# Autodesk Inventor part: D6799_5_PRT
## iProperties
Created: 2007-03
Part Number: D6799_5_PRT
Document SubType Name: Modeling
Designer: Andy Moles
Material: Steel
Mass: 0.239394 g
Surface Area: 1.23593 cm^2
Volume: 0.030496 cm^3
Density: 7.85 g/cm^3
Author: Andy Moles
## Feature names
1. Base1
